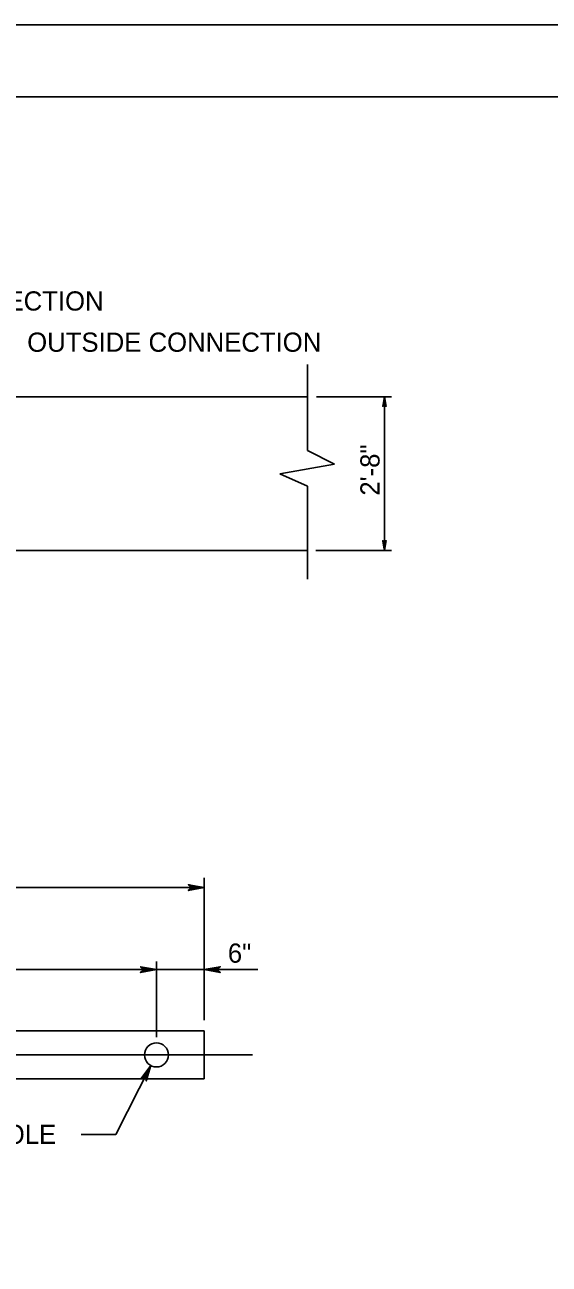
# Model space of a CAD drawing. Extents: x 499881 to 500993, y 499985 to 500645.
# Drawn here: x 500285 to 500394.1, y 500387 to 500645 of the extents above; entities that cross this region are included whole.
import ezdxf

# ---------------------------------------------------------------- set-up
doc = ezdxf.new("R2010")
doc.units = 0
for name, color, linetype in [('1', 7, 'Continuous'), ('2', 7, 'Continuous'), ('24', 7, 'Continuous'), ('3', 7, 'Continuous'), ('41', 7, 'Continuous'), ('5', 7, 'Continuous')]:
    doc.layers.add(name, color=color, linetype=linetype)

msp = doc.modelspace()

# ---------------------------------------------------------------- linework, layer by layer
at = {"layer": '1'}
for p, q in [((499944.83, 500645), (500993, 500645)), ((500990, 500630), (500000, 500630))]:
    msp.add_line(p, q, dxfattribs=at)
at = {"layer": '2'}
for points in [[(500322.33, 500465.37), (500319, 500464.79), (500319.8, 500465.37), (500319.02, 500465.95), (500322.33, 500465.37), (500322.11, 500465.38), (500319.1, 500464.83), (500319.86, 500465.38), (500319.16, 500465.91), (500321.99, 500465.39), (500321.88, 500465.37), (500319.3, 500464.91), (500319.88, 500465.38), (500319.28, 500465.83), (500321.83, 500465.37), (500321.72, 500465.39), (500319.46, 500464.98), (500319.9, 500465.37), (500319.45, 500465.78), (500321.39, 500465.39), (500321.21, 500465.39), (500319.63, 500465.07), (500319.94, 500465.36), (500319.61, 500465.69), (500321.17, 500465.37), (500321, 500465.36), (500319.81, 500465.16), (500320.04, 500465.39), (500319.79, 500465.62), (500320.83, 500465.37), (500320.67, 500465.36), (500319.95, 500465.22), (500320.07, 500465.38), (500319.88, 500465.56), (500320.58, 500465.37), (500320.11, 500465.26), (500320.18, 500465.39), (500319.98, 500465.52), (500320.46, 500465.39), (500320.16, 500465.31), (500320.28, 500465.41), (500320.14, 500465.47), (500320.28, 500465.38), (500320.21, 500465.36)], [(500312.36, 500448.3), (500309.04, 500447.71), (500309.83, 500448.3), (500309.06, 500448.88), (500312.36, 500448.3), (500312.14, 500448.31), (500309.13, 500447.76), (500309.9, 500448.31), (500309.19, 500448.83), (500312.02, 500448.32), (500311.91, 500448.3), (500309.33, 500447.84), (500309.91, 500448.31), (500309.32, 500448.76), (500311.86, 500448.3), (500311.75, 500448.32), (500309.5, 500447.91), (500309.94, 500448.3), (500309.49, 500448.71), (500311.43, 500448.32), (500311.24, 500448.32), (500309.67, 500448), (500309.97, 500448.29), (500309.64, 500448.62), (500311.21, 500448.3), (500311.03, 500448.29), (500309.85, 500448.09), (500310.07, 500448.32), (500309.83, 500448.55), (500310.87, 500448.3), (500310.7, 500448.28), (500309.99, 500448.15), (500310.11, 500448.31), (500309.91, 500448.49), (500310.62, 500448.3), (500310.15, 500448.19), (500310.22, 500448.32), (500310.01, 500448.45), (500310.5, 500448.32), (500310.19, 500448.24), (500310.32, 500448.34), (500310.17, 500448.4), (500310.32, 500448.31), (500310.24, 500448.29)], [(500322.33, 500448.3), (500325.65, 500447.71), (500324.86, 500448.3), (500325.63, 500448.88), (500322.33, 500448.3), (500322.55, 500448.31), (500325.56, 500447.76), (500324.79, 500448.31), (500325.5, 500448.83), (500322.67, 500448.32), (500322.78, 500448.3), (500325.36, 500447.84), (500324.78, 500448.31), (500325.37, 500448.76), (500322.83, 500448.3), (500322.94, 500448.32), (500325.19, 500447.91), (500324.75, 500448.3), (500325.2, 500448.71), (500323.26, 500448.32), (500323.45, 500448.32), (500325.03, 500448), (500324.72, 500448.29), (500325.05, 500448.62), (500323.48, 500448.3), (500323.66, 500448.29), (500324.85, 500448.09), (500324.62, 500448.32), (500324.86, 500448.55), (500323.82, 500448.3), (500323.99, 500448.28), (500324.7, 500448.15), (500324.58, 500448.31), (500324.78, 500448.49), (500324.08, 500448.3), (500324.54, 500448.19), (500324.47, 500448.32), (500324.68, 500448.45), (500324.19, 500448.32), (500324.5, 500448.24), (500324.37, 500448.34), (500324.52, 500448.4), (500324.37, 500448.31), (500324.45, 500448.29)], [(500311.22, 500428.31), (500309.2, 500425.61), (500310.08, 500426.06), (500310.25, 500425.1), (500311.22, 500428.31), (500311.13, 500428.11), (500309.28, 500425.68), (500310.12, 500426.11), (500310.27, 500425.24), (500311.08, 500428), (500311.02, 500427.91), (500309.45, 500425.82), (500310.12, 500426.12), (500310.26, 500425.39), (500311, 500427.87), (500310.96, 500427.76), (500309.58, 500425.93), (500310.13, 500426.15), (500310.29, 500425.56), (500310.82, 500427.47), (500310.73, 500427.31), (500309.73, 500426.04), (500310.14, 500426.18), (500310.28, 500425.74), (500310.7, 500427.28), (500310.61, 500427.13), (500309.9, 500426.16), (500310.2, 500426.26), (500310.3, 500425.94), (500310.55, 500426.98), (500310.46, 500426.84), (500310.01, 500426.26), (500310.21, 500426.3), (500310.28, 500426.04), (500310.43, 500426.75), (500310.13, 500426.39), (500310.27, 500426.39), (500310.29, 500426.15), (500310.4, 500426.64), (500310.19, 500426.4), (500310.34, 500426.47), (500310.33, 500426.31), (500310.31, 500426.49), (500310.26, 500426.43)]]:
    msp.add_lwpolyline(points, dxfattribs=at)
at = {"layer": '24'}
for points in [[(500359.81, 500567.55), (500359.46, 500565.54), (500359.81, 500566.02), (500360.16, 500565.55), (500359.81, 500567.55), (500359.81, 500567.42), (500359.48, 500565.6), (500359.82, 500566.06), (500360.13, 500565.64), (500359.82, 500567.35), (500359.81, 500567.28), (500359.53, 500565.72), (500359.82, 500566.07), (500360.09, 500565.71), (500359.81, 500567.25), (500359.82, 500567.18), (500359.58, 500565.82), (500359.81, 500566.09), (500360.06, 500565.82), (500359.82, 500566.99), (500359.82, 500566.88), (500359.63, 500565.92), (500359.81, 500566.11), (500360.01, 500565.91), (500359.81, 500566.86), (500359.81, 500566.75), (500359.68, 500566.03), (500359.82, 500566.17), (500359.96, 500566.02), (500359.81, 500566.65), (500359.8, 500566.55), (500359.72, 500566.12), (500359.82, 500566.19), (500359.92, 500566.07), (500359.81, 500566.5), (500359.74, 500566.22), (500359.82, 500566.26), (500359.9, 500566.13), (500359.82, 500566.43), (500359.78, 500566.24), (500359.84, 500566.32), (500359.87, 500566.23), (500359.82, 500566.32), (500359.81, 500566.27)], [(500359.81, 500567.55), (500359.46, 500565.54), (500359.81, 500566.02), (500360.16, 500565.55), (500359.81, 500567.55), (500359.81, 500567.42), (500359.48, 500565.6), (500359.82, 500566.06), (500360.13, 500565.64), (500359.82, 500567.35), (500359.81, 500567.28), (500359.53, 500565.72), (500359.82, 500566.07), (500360.09, 500565.71), (500359.81, 500567.25), (500359.82, 500567.18), (500359.58, 500565.82), (500359.81, 500566.09), (500360.06, 500565.82), (500359.82, 500566.99), (500359.82, 500566.88), (500359.63, 500565.92), (500359.81, 500566.11), (500360.01, 500565.91), (500359.81, 500566.86), (500359.81, 500566.75), (500359.68, 500566.03), (500359.82, 500566.17), (500359.96, 500566.02), (500359.81, 500566.65), (500359.8, 500566.55), (500359.72, 500566.12), (500359.82, 500566.19), (500359.92, 500566.07), (500359.81, 500566.5), (500359.74, 500566.22), (500359.82, 500566.26), (500359.9, 500566.13), (500359.82, 500566.43), (500359.78, 500566.24), (500359.84, 500566.32), (500359.87, 500566.23), (500359.82, 500566.32), (500359.81, 500566.27)], [(500359.81, 500535.6), (500360.17, 500537.61), (500359.81, 500537.13), (500359.46, 500537.6), (500359.81, 500535.6), (500359.81, 500535.73), (500360.14, 500537.55), (500359.81, 500537.09), (500359.49, 500537.52), (500359.8, 500535.8), (500359.81, 500535.87), (500360.09, 500537.43), (500359.81, 500537.08), (500359.53, 500537.44), (500359.81, 500535.9), (500359.8, 500535.97), (500360.05, 500537.33), (500359.81, 500537.07), (500359.57, 500537.34), (500359.8, 500536.16), (500359.8, 500536.28), (500360, 500537.23), (500359.82, 500537.04), (500359.62, 500537.24), (500359.81, 500536.3), (500359.82, 500536.4), (500359.94, 500537.12), (500359.8, 500536.98), (500359.66, 500537.13), (500359.81, 500536.5), (500359.82, 500536.6), (500359.9, 500537.03), (500359.81, 500536.96), (500359.7, 500537.08), (500359.81, 500536.66), (500359.88, 500536.94), (500359.8, 500536.9), (500359.72, 500537.02), (500359.8, 500536.73), (500359.85, 500536.91), (500359.79, 500536.83), (500359.75, 500536.92), (500359.81, 500536.83), (500359.82, 500536.88)]]:
    msp.add_lwpolyline(points, dxfattribs=at)
at = {"layer": '3'}
for p, q in [((500343.81, 500556.39), (500343.81, 500574.24)), ((500200.81, 500567.57), (500343.81, 500567.57)), ((500345.71, 500567.57), (500360.23, 500567.57)), ((500359.81, 500567.55), (500359.81, 500535.6)), ((500343.81, 500556.39), (500349.42, 500553.51)), ((500349.42, 500553.51), (500338.08, 500551.48)), ((500338.08, 500551.48), (500343.81, 500548.94)), ((500343.81, 500548.94), (500343.81, 500529.58)), ((500200.81, 500535.58), (500343.81, 500535.58)), ((500345.56, 500535.58), (500361.27, 500535.58)), ((500322.33, 500437.74), (500322.33, 500467.42)), ((500322.33, 500465.37), (500082.33, 500465.37)), ((500312.36, 500448.3), (500227.33, 500448.3)), ((500322.33, 500448.3), (500312.36, 500448.3)), ((500312.37, 500434.25), (500312.37, 500449.99)), ((500333.47, 500448.3), (500322.33, 500448.3)), ((500322.33, 500435.53), (500082.33, 500435.53)), ((500322.33, 500425.53), (500322.33, 500435.53)), ((500311.23, 500428.3), (500303.88, 500413.95)), ((500082.33, 500425.53), (500322.33, 500425.53)), ((500303.88, 500413.95), (500296.69, 500413.95))]:
    msp.add_line(p, q, dxfattribs=at)
msp.add_circle((500312.37, 500430.52), 2.5, dxfattribs=at)
at = {"layer": '41'}
msp.add_lwpolyline([(499944.83, 499985), (500993, 499985), (500993, 500645), (499944.83, 500645)], close=True, dxfattribs=at)
at = {"layer": '5'}
for p, q in [((500360.23, 500567.57), (500361.31, 500567.57)), ((500072.33, 500430.53), (500332.33, 500430.53))]:
    msp.add_line(p, q, dxfattribs=at)

# ---------------------------------------------------------------- texts
at = {"layer": '3'}
for s, p in [('INSIDE CONNECTION', (500246.09, 500585.5)), ('OUTSIDE CONNECTION', (500285.46, 500576.92)), ('6"', (500327.23, 500449.72)), ('3" DIA. HOLE', (500258.68, 500411.99))]:
    msp.add_text(s, height=4, dxfattribs=at).set_placement(p)
msp.add_text('2\'-8"', height=4, rotation=90, dxfattribs=at).set_placement((500358.81, 500546.97))

doc.saveas('drawing.dxf')
